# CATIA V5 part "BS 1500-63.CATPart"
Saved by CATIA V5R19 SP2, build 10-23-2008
Part number: BS 1500-63
Bounding box of the stored display mesh (mm): x -31.459 to 31.459, y -31.459 to 31.459, z 0 to 170
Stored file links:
  C:\Users\Bora\Desktop\3D Katı model\BS serisi\BS 1500\BS 1500-63.CATPart
  C:\Program Files\Dassault Systemes\B19\intel_a\reffiles\standard\MetricThickPitch.txt
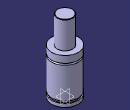
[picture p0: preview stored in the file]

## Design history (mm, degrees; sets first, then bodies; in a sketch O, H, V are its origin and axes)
Body1 (main body)
  Sketch1 on yz-plane, origin (0, 0, 0), H (0, 1, 0), V (0, 0, 1)
    point P1 (31.5, 90)
    point P2 (31.5, 86)
    point P3 (31.5, 90)
    point P7 (18, 169)
    point P9 (18, 169)
    point P14 (31.5, 86)
    arc A1 centre (31.5, 88) radius 2 from (31.5, 90) to (31.5, 86) ccw
    line L1 (31.5, 90) -> (31.5, 106)
    line L2 (31.5, 0) -> (31.5, 8)
    arc A2 centre (17, 169) radius 1 from (18, 169) to (17, 170) ccw
    line L3 (18, 169) -> (18, 106)
    line L4 (29, 13) -> (29, 8)
    line L5 (31.5, 13) -> (31.5, 86)
    line L6 (17, 170) -> (0, 170)
    point P15 (0, 170)
    line L7 (18, 106) -> (31.5, 106)
    line L8 (0, 0) -> (31.5, 0)
    line L9 (29, 13) -> (31.5, 13)
    line L10 (29, 8) -> (31.5, 8)
    coincidence: P15 V, P1 P3, P2 P14, P7 P9
    tangency: L6 A2
    horizontal: L7 H, L8 H, L9 H, L10 H
  Shaft1: profile Sketch1, axis Sketch1.V, angle 360
  Sketch2 on face of Shaft1 from Sketch1.L8, origin (0, 0, 0), H (1, 0, 0), V (0, -1, 0)
    point P1 (10, 0)
    distance P1 V = 10
  Hole1: placed by Sketch2, at (10, 0, 0) direction (0, 0, 1), diameter 6.647, depth 5, threaded "M8", thread diameter 8, thread depth 5, pitch 1.25
  CircPattern1: of Hole1, instances 2, angular step 180, axis from xy-plane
